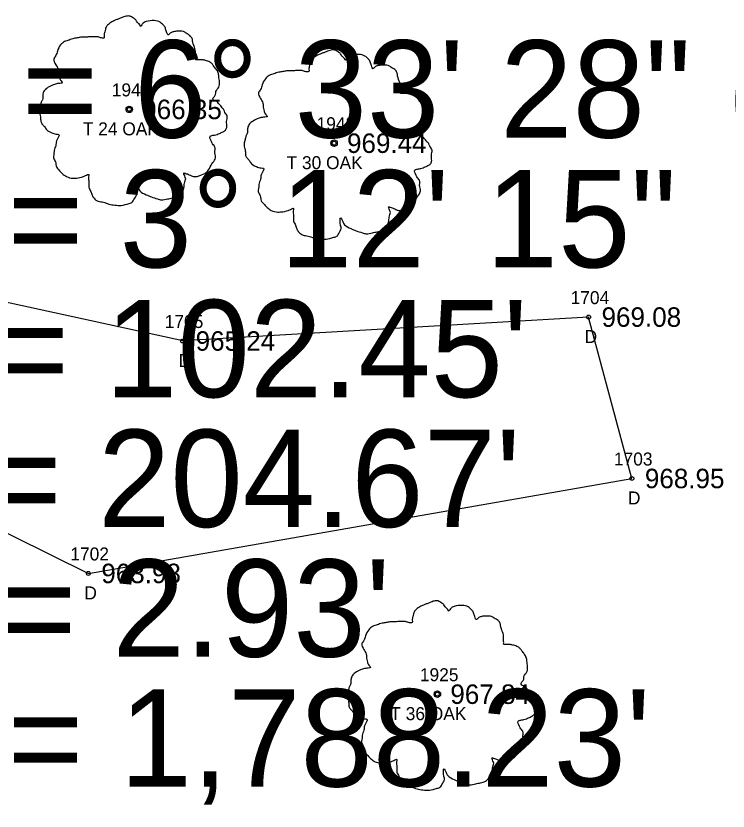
# Model space of a CAD drawing. Extents: x 1528109 to 1531398, y 1157799 to 1162548.
# Drawn here: x 1530656.7 to 1530711.6, y 1158820.1 to 1158881.4 of the extents above; entities that cross this region are included whole.
import ezdxf

# ---------------------------------------------------------------- set-up
doc = ezdxf.new("R2010")
doc.units = 0
for name, color, linetype in [('RD_EX_Driveway', 7, 'Continuous'), ('RD_EX_Driveway_txCode', 7, 'Continuous'), ('RD_EX_TX_Driveway_ELEV', 7, 'Continuous'), ('RD_EX_TX_VEG_ELEV', 7, 'Continuous'), ('RD_EX_VEG', 7, 'Continuous'), ('RD_EX_VEG_txCode', 7, 'Continuous'), ('RD_HC_Cl', 7, 'Continuous'), ('RD_HC_Data', 7, 'Continuous'), ('RD_SMD_Locator', 7, 'Continuous')]:
    doc.layers.add(name, color=color, linetype=linetype)

msp = doc.modelspace()

# ---------------------------------------------------------------- linework, layer by layer
at = {"layer": 'RD_EX_Driveway'}
msp.add_lwpolyline([(1530632.946, 1158850.037), (1530641.869, 1158848.504), (1530662.26, 1158838.421), (1530704.169, 1158845.738), (1530700.829, 1158858.174), (1530669.534, 1158856.332), (1530636.658, 1158863.52), (1530628.109, 1158867.33)], dxfattribs=at)
at = {"layer": 'RD_EX_VEG'}
for centre, radius in [((1530665.416, 1158874.178), 0.25), ((1530665.403, 1158874.16), 0.0001), ((1530681.204, 1158871.571), 0.25), ((1530681.191, 1158871.552), 0.0001), ((1530689.17, 1158829.117), 0.25), ((1530689.158, 1158829.099), 0.0001)]:
    msp.add_circle(centre, radius, dxfattribs=at)
for points in [[(1530665.548, 1158881.346), (1530665.248, 1158881.371), (1530664.923, 1158881.271), (1530664.673, 1158881.171), (1530664.448, 1158881.096), (1530664.223, 1158880.996), (1530663.923, 1158880.821), (1530663.698, 1158880.621), (1530663.573, 1158880.371), (1530663.523, 1158880.146), (1530663.474, 1158879.871), (1530663.474, 1158879.696), (1530663.349, 1158879.671), (1530663.199, 1158879.696), (1530662.949, 1158879.771), (1530662.699, 1158879.771), (1530662.449, 1158879.771), (1530662.099, 1158879.746), (1530661.749, 1158879.746), (1530661.474, 1158879.696), (1530661.15, 1158879.646), (1530660.775, 1158879.521), (1530660.425, 1158879.396), (1530660.125, 1158879.147), (1530659.875, 1158878.672), (1530659.75, 1158878.322), (1530659.6, 1158878.072), (1530659.75, 1158877.622), (1530659.925, 1158877.272), (1530659.95, 1158877.072), (1530660.025, 1158876.648), (1530660.125, 1158876.423), (1530660.25, 1158876.223), (1530660.175, 1158876.198), (1530659.8, 1158876.148), (1530659.5, 1158876.048), (1530659.075, 1158875.823), (1530658.851, 1158875.598), (1530658.751, 1158875.273), (1530658.726, 1158874.923), (1530658.626, 1158874.724), (1530658.551, 1158874.449), (1530658.526, 1158874.374), (1530658.476, 1158874.049), (1530658.576, 1158873.599), (1530658.601, 1158873.249), (1530658.726, 1158873.024), (1530658.876, 1158872.849), (1530659.05, 1158872.599), (1530659.45, 1158872.375), (1530659.775, 1158872.275), (1530659.975, 1158872.25), (1530659.8, 1158871.75), (1530659.75, 1158871.4), (1530659.625, 1158871), (1530659.625, 1158870.925), (1530659.575, 1158870.45), (1530659.725, 1158870.125), (1530659.8, 1158869.751), (1530659.975, 1158869.526), (1530660.25, 1158869.226), (1530660.575, 1158869.001), (1530661.075, 1158868.876), (1530661.474, 1158868.901), (1530662.049, 1158869.076), (1530662.299, 1158869.151), (1530662.274, 1158868.976), (1530662.299, 1158868.601), (1530662.299, 1158868.176), (1530662.449, 1158867.852), (1530662.549, 1158867.577), (1530662.699, 1158867.327), (1530663.024, 1158867.102), (1530663.424, 1158867.027), (1530663.848, 1158866.877), (1530664.298, 1158866.802), (1530664.798, 1158866.777), (1530665.398, 1158866.927), (1530665.673, 1158867.052), (1530665.773, 1158867.227), (1530665.972, 1158867.602), (1530665.922, 1158867.827), (1530665.947, 1158868.426), (1530666.047, 1158868.251), (1530666.222, 1158867.901), (1530666.722, 1158867.602), (1530667.122, 1158867.427), (1530667.597, 1158867.277), (1530667.897, 1158867.202), (1530668.371, 1158867.277), (1530668.746, 1158867.352), (1530669.121, 1158867.477), (1530669.421, 1158867.752), (1530669.596, 1158868.026), (1530669.646, 1158868.301), (1530669.721, 1158868.676), (1530669.771, 1158868.851)], [(1530669.771, 1158868.851), (1530669.696, 1158869.026), (1530669.646, 1158869.276), (1530669.721, 1158869.251), (1530669.896, 1158869.201), (1530670.171, 1158869.076), (1530670.396, 1158869.001), (1530670.72, 1158869.026), (1530670.995, 1158869.126), (1530671.445, 1158869.401), (1530671.72, 1158869.876), (1530671.995, 1158870.275), (1530672.07, 1158870.6), (1530672.02, 1158870.825), (1530671.995, 1158871.325), (1530671.795, 1158871.575), (1530671.745, 1158871.7), (1530671.645, 1158872.1), (1530671.72, 1158872.15), (1530671.995, 1158872.2), (1530672.37, 1158872.325), (1530672.645, 1158872.449), (1530672.869, 1158872.624), (1530672.944, 1158872.849), (1530672.919, 1158873.249), (1530672.969, 1158873.649), (1530672.894, 1158873.799), (1530672.794, 1158873.949), (1530672.719, 1158874.149), (1530672.57, 1158874.299), (1530672.47, 1158874.449), (1530672.37, 1158874.549), (1530672.245, 1158874.699), (1530672.07, 1158874.823), (1530671.92, 1158874.873), (1530671.87, 1158875.023), (1530672.02, 1158875.223), (1530672.07, 1158875.323), (1530672.095, 1158875.548), (1530672.32, 1158875.898), (1530672.37, 1158876.298), (1530672.32, 1158876.723), (1530672.27, 1158876.998), (1530672.12, 1158877.272), (1530671.92, 1158877.522), (1530671.795, 1158877.697), (1530671.62, 1158877.822), (1530671.295, 1158877.947), (1530671.045, 1158877.997), (1530670.695, 1158877.997), (1530670.495, 1158878.047), (1530670.52, 1158878.097), (1530670.52, 1158878.247), (1530670.52, 1158878.522), (1530670.445, 1158878.972), (1530670.296, 1158879.471), (1530670.296, 1158879.496), (1530670.196, 1158879.746), (1530669.971, 1158879.946), (1530669.796, 1158880.046), (1530669.596, 1158880.171), (1530669.346, 1158880.196), (1530669.046, 1158880.196), (1530668.771, 1158880.146), (1530668.571, 1158880.046), (1530668.396, 1158879.921), (1530668.321, 1158880.071), (1530668.221, 1158880.371), (1530668.171, 1158880.521), (1530668.022, 1158880.696), (1530667.797, 1158880.896), (1530667.347, 1158881.021), (1530666.722, 1158880.946), (1530666.422, 1158880.746), (1530666.272, 1158880.571), (1530666.222, 1158880.696), (1530666.022, 1158880.896), (1530665.922, 1158881.071), (1530665.748, 1158881.196), (1530665.598, 1158881.296), (1530665.498, 1158881.346)], [(1530681.336, 1158878.738), (1530681.036, 1158878.763), (1530680.711, 1158878.663), (1530680.461, 1158878.563), (1530680.236, 1158878.488), (1530680.011, 1158878.388), (1530679.711, 1158878.214), (1530679.487, 1158878.014), (1530679.362, 1158877.764), (1530679.312, 1158877.539), (1530679.262, 1158877.264), (1530679.262, 1158877.089), (1530679.137, 1158877.064), (1530678.987, 1158877.089), (1530678.737, 1158877.164), (1530678.487, 1158877.164), (1530678.237, 1158877.164), (1530677.887, 1158877.139), (1530677.537, 1158877.139), (1530677.263, 1158877.089), (1530676.938, 1158877.039), (1530676.563, 1158876.914), (1530676.213, 1158876.789), (1530675.913, 1158876.539), (1530675.663, 1158876.064), (1530675.538, 1158875.715), (1530675.388, 1158875.465), (1530675.538, 1158875.015), (1530675.713, 1158874.665), (1530675.738, 1158874.465), (1530675.813, 1158874.04), (1530675.913, 1158873.815), (1530676.038, 1158873.615), (1530675.963, 1158873.591), (1530675.588, 1158873.541), (1530675.288, 1158873.441), (1530674.864, 1158873.216), (1530674.639, 1158872.991), (1530674.539, 1158872.666), (1530674.514, 1158872.316), (1530674.414, 1158872.116), (1530674.339, 1158871.841), (1530674.314, 1158871.766), (1530674.264, 1158871.441), (1530674.364, 1158870.992), (1530674.389, 1158870.642), (1530674.514, 1158870.417), (1530674.664, 1158870.242), (1530674.839, 1158869.992), (1530675.238, 1158869.767), (1530675.563, 1158869.667), (1530675.763, 1158869.642), (1530675.588, 1158869.142), (1530675.538, 1158868.793), (1530675.413, 1158868.393), (1530675.413, 1158868.318), (1530675.363, 1158867.843), (1530675.513, 1158867.518), (1530675.588, 1158867.143), (1530675.763, 1158866.918), (1530676.038, 1158866.619), (1530676.363, 1158866.394), (1530676.863, 1158866.269), (1530677.263, 1158866.294), (1530677.837, 1158866.469), (1530678.087, 1158866.544), (1530678.062, 1158866.369), (1530678.087, 1158865.994), (1530678.087, 1158865.569), (1530678.237, 1158865.244), (1530678.337, 1158864.969), (1530678.487, 1158864.719), (1530678.812, 1158864.495), (1530679.212, 1158864.42), (1530679.636, 1158864.27), (1530680.086, 1158864.195), (1530680.586, 1158864.17), (1530681.186, 1158864.32), (1530681.461, 1158864.445), (1530681.561, 1158864.619), (1530681.761, 1158864.994), (1530681.711, 1158865.219), (1530681.736, 1158865.819), (1530681.835, 1158865.644), (1530682.01, 1158865.294), (1530682.51, 1158864.994), (1530682.91, 1158864.819), (1530683.385, 1158864.669), (1530683.685, 1158864.594), (1530684.159, 1158864.669), (1530684.534, 1158864.744), (1530684.909, 1158864.869), (1530685.209, 1158865.144), (1530685.384, 1158865.419), (1530685.434, 1158865.694), (1530685.509, 1158866.069), (1530685.559, 1158866.244)], [(1530685.559, 1158866.244), (1530685.484, 1158866.419), (1530685.434, 1158866.669), (1530685.509, 1158866.644), (1530685.684, 1158866.594), (1530685.959, 1158866.469), (1530686.184, 1158866.394), (1530686.508, 1158866.419), (1530686.783, 1158866.519), (1530687.233, 1158866.794), (1530687.508, 1158867.268), (1530687.783, 1158867.668), (1530687.858, 1158867.993), (1530687.808, 1158868.218), (1530687.783, 1158868.718), (1530687.583, 1158868.968), (1530687.533, 1158869.092), (1530687.433, 1158869.492), (1530687.508, 1158869.542), (1530687.783, 1158869.592), (1530688.158, 1158869.717), (1530688.433, 1158869.842), (1530688.658, 1158870.017), (1530688.732, 1158870.242), (1530688.708, 1158870.642), (1530688.757, 1158871.042), (1530688.683, 1158871.192), (1530688.583, 1158871.341), (1530688.508, 1158871.541), (1530688.358, 1158871.691), (1530688.258, 1158871.841), (1530688.158, 1158871.941), (1530688.033, 1158872.091), (1530687.858, 1158872.216), (1530687.708, 1158872.266), (1530687.658, 1158872.416), (1530687.808, 1158872.616), (1530687.858, 1158872.716), (1530687.883, 1158872.941), (1530688.108, 1158873.291), (1530688.158, 1158873.69), (1530688.108, 1158874.115), (1530688.058, 1158874.39), (1530687.908, 1158874.665), (1530687.708, 1158874.915), (1530687.583, 1158875.09), (1530687.408, 1158875.215), (1530687.083, 1158875.34), (1530686.833, 1158875.39), (1530686.483, 1158875.39), (1530686.284, 1158875.44), (1530686.309, 1158875.49), (1530686.309, 1158875.64), (1530686.309, 1158875.915), (1530686.234, 1158876.364), (1530686.084, 1158876.864), (1530686.084, 1158876.889), (1530685.984, 1158877.139), (1530685.759, 1158877.339), (1530685.584, 1158877.439), (1530685.384, 1158877.564), (1530685.134, 1158877.589), (1530684.834, 1158877.589), (1530684.559, 1158877.539), (1530684.359, 1158877.439), (1530684.184, 1158877.314), (1530684.109, 1158877.464), (1530684.01, 1158877.764), (1530683.96, 1158877.914), (1530683.81, 1158878.089), (1530683.585, 1158878.288), (1530683.135, 1158878.413), (1530682.51, 1158878.338), (1530682.21, 1158878.139), (1530682.06, 1158877.964), (1530682.01, 1158878.089), (1530681.81, 1158878.288), (1530681.711, 1158878.463), (1530681.536, 1158878.588), (1530681.386, 1158878.688), (1530681.286, 1158878.738)], [(1530689.302, 1158836.285), (1530689.002, 1158836.31), (1530688.678, 1158836.21), (1530688.428, 1158836.11), (1530688.203, 1158836.035), (1530687.978, 1158835.935), (1530687.678, 1158835.76), (1530687.453, 1158835.56), (1530687.328, 1158835.31), (1530687.278, 1158835.085), (1530687.228, 1158834.81), (1530687.228, 1158834.635), (1530687.103, 1158834.61), (1530686.953, 1158834.635), (1530686.703, 1158834.71), (1530686.454, 1158834.71), (1530686.204, 1158834.71), (1530685.854, 1158834.685), (1530685.504, 1158834.685), (1530685.229, 1158834.635), (1530684.904, 1158834.585), (1530684.529, 1158834.46), (1530684.18, 1158834.335), (1530683.88, 1158834.086), (1530683.63, 1158833.611), (1530683.505, 1158833.261), (1530683.355, 1158833.011), (1530683.505, 1158832.561), (1530683.68, 1158832.211), (1530683.705, 1158832.011), (1530683.78, 1158831.587), (1530683.88, 1158831.362), (1530684.005, 1158831.162), (1530683.93, 1158831.137), (1530683.555, 1158831.087), (1530683.255, 1158830.987), (1530682.83, 1158830.762), (1530682.605, 1158830.537), (1530682.505, 1158830.212), (1530682.48, 1158829.862), (1530682.38, 1158829.663), (1530682.305, 1158829.388), (1530682.28, 1158829.313), (1530682.23, 1158828.988), (1530682.33, 1158828.538), (1530682.355, 1158828.188), (1530682.48, 1158827.963), (1530682.63, 1158827.788), (1530682.805, 1158827.538), (1530683.205, 1158827.314), (1530683.53, 1158827.214), (1530683.73, 1158827.189), (1530683.555, 1158826.689), (1530683.505, 1158826.339), (1530683.38, 1158825.939), (1530683.38, 1158825.864), (1530683.33, 1158825.389), (1530683.48, 1158825.064), (1530683.555, 1158824.69), (1530683.73, 1158824.465), (1530684.005, 1158824.165), (1530684.329, 1158823.94), (1530684.829, 1158823.815), (1530685.229, 1158823.84), (1530685.804, 1158824.015), (1530686.054, 1158824.09), (1530686.029, 1158823.915), (1530686.054, 1158823.54), (1530686.054, 1158823.115), (1530686.204, 1158822.791), (1530686.304, 1158822.516), (1530686.454, 1158822.266), (1530686.778, 1158822.041), (1530687.178, 1158821.966), (1530687.603, 1158821.816), (1530688.053, 1158821.741), (1530688.553, 1158821.716), (1530689.152, 1158821.866), (1530689.427, 1158821.991), (1530689.527, 1158822.166), (1530689.727, 1158822.541), (1530689.677, 1158822.766), (1530689.702, 1158823.365), (1530689.802, 1158823.19), (1530689.977, 1158822.84), (1530690.477, 1158822.541), (1530690.877, 1158822.366), (1530691.351, 1158822.216), (1530691.651, 1158822.141), (1530692.126, 1158822.216), (1530692.501, 1158822.291), (1530692.876, 1158822.416), (1530693.176, 1158822.691), (1530693.351, 1158822.965), (1530693.401, 1158823.24), (1530693.475, 1158823.615), (1530693.525, 1158823.79)], [(1530693.525, 1158823.79), (1530693.451, 1158823.965), (1530693.401, 1158824.215), (1530693.475, 1158824.19), (1530693.65, 1158824.14), (1530693.925, 1158824.015), (1530694.15, 1158823.94), (1530694.475, 1158823.965), (1530694.75, 1158824.065), (1530695.2, 1158824.34), (1530695.475, 1158824.815), (1530695.749, 1158825.214), (1530695.824, 1158825.539), (1530695.774, 1158825.764), (1530695.749, 1158826.264), (1530695.55, 1158826.514), (1530695.5, 1158826.639), (1530695.4, 1158827.039), (1530695.475, 1158827.089), (1530695.749, 1158827.139), (1530696.124, 1158827.264), (1530696.399, 1158827.388), (1530696.624, 1158827.563), (1530696.699, 1158827.788), (1530696.674, 1158828.188), (1530696.724, 1158828.588), (1530696.649, 1158828.738), (1530696.549, 1158828.888), (1530696.474, 1158829.088), (1530696.324, 1158829.238), (1530696.224, 1158829.388), (1530696.124, 1158829.488), (1530695.999, 1158829.638), (1530695.824, 1158829.762), (1530695.675, 1158829.812), (1530695.625, 1158829.962), (1530695.774, 1158830.162), (1530695.824, 1158830.262), (1530695.849, 1158830.487), (1530696.074, 1158830.837), (1530696.124, 1158831.237), (1530696.074, 1158831.662), (1530696.024, 1158831.937), (1530695.874, 1158832.211), (1530695.675, 1158832.461), (1530695.55, 1158832.636), (1530695.375, 1158832.761), (1530695.05, 1158832.886), (1530694.8, 1158832.936), (1530694.45, 1158832.936), (1530694.25, 1158832.986), (1530694.275, 1158833.036), (1530694.275, 1158833.186), (1530694.275, 1158833.461), (1530694.2, 1158833.911), (1530694.05, 1158834.41), (1530694.05, 1158834.435), (1530693.95, 1158834.685), (1530693.725, 1158834.885), (1530693.55, 1158834.985), (1530693.351, 1158835.11), (1530693.101, 1158835.135), (1530692.801, 1158835.135), (1530692.526, 1158835.085), (1530692.326, 1158834.985), (1530692.151, 1158834.86), (1530692.076, 1158835.01), (1530691.976, 1158835.31), (1530691.926, 1158835.46), (1530691.776, 1158835.635), (1530691.551, 1158835.835), (1530691.101, 1158835.96), (1530690.477, 1158835.885), (1530690.177, 1158835.685), (1530690.027, 1158835.51), (1530689.977, 1158835.635), (1530689.777, 1158835.835), (1530689.677, 1158836.01), (1530689.502, 1158836.135), (1530689.352, 1158836.235), (1530689.252, 1158836.285)]]:
    msp.add_spline(points, degree=3, dxfattribs=at)
at = {"layer": 'RD_HC_Cl'}
msp.add_arc((1528951.998, 1158192.727), 1788.23, 15.397279, 21.95502, dxfattribs=at)
at = {"layer": 'RD_SMD_Locator'}
for centre in [(1530665.416, 1158874.178), (1530681.204, 1158871.571), (1530700.829, 1158858.174), (1530669.534, 1158856.332), (1530704.169, 1158845.738), (1530662.26, 1158838.421), (1530689.17, 1158829.117)]:
    msp.add_circle(centre, 0.15, dxfattribs=at)

# ---------------------------------------------------------------- texts
at = {"layer": 'RD_EX_Driveway_txCode'}
for s, p in [('1704', (1530699.443, 1158859.174)), ('1705', (1530668.148, 1158857.332)), ('D', (1530700.522, 1158856.174)), ('D', (1530669.226, 1158854.332)), ('1703', (1530702.783, 1158846.738)), ('D', (1530703.862, 1158843.738)), ('1702', (1530660.874, 1158839.421)), ('D', (1530661.953, 1158836.421))]:
    msp.add_text(s, height=1, dxfattribs=at).set_placement(p)
at = {"layer": 'RD_EX_TX_Driveway_ELEV'}
for s, p in [('969.08', (1530701.829, 1158857.424)), ('965.24', (1530670.534, 1158855.582)), ('968.95', (1530705.169, 1158844.988)), ('963.98', (1530663.26, 1158837.671))]:
    msp.add_text(s, height=1.5, dxfattribs=at).set_placement(p)
at = {"layer": 'RD_EX_TX_VEG_ELEV'}
for s, p in [('966.35', (1530666.416, 1158873.428)), ('969.44', (1530682.204, 1158870.821)), ('967.84', (1530690.17, 1158828.367))]:
    msp.add_text(s, height=1.5, dxfattribs=at).set_placement(p)
at = {"layer": 'RD_EX_VEG_txCode'}
for s, p in [('1942', (1530664.069, 1158875.178)), ('T 24 OAK', (1530661.833, 1158872.178)), ('1943', (1530679.857, 1158872.571)), ('T 30 OAK', (1530677.542, 1158869.571)), ('1925', (1530687.824, 1158830.117)), ('T 36 OAK', (1530685.54, 1158827.117))]:
    msp.add_text(s, height=1, dxfattribs=at).set_placement(p)
at = {"layer": 'RD_HC_Data'}
for s, p in [('    = 6%%d 33\' 28" (LT)', (1530646, 1158872)), ('D = 3%%d 12\' 15"', (1530646, 1158862)), ("T = 102.45'", (1530646, 1158852)), ("L = 204.67'", (1530646, 1158842)), ("E = 2.93'", (1530646, 1158832)), ("R = 1,788.23'", (1530646, 1158822))]:
    msp.add_text(s, height=7.5, dxfattribs=at).set_placement(p)

doc.saveas('drawing.dxf')
